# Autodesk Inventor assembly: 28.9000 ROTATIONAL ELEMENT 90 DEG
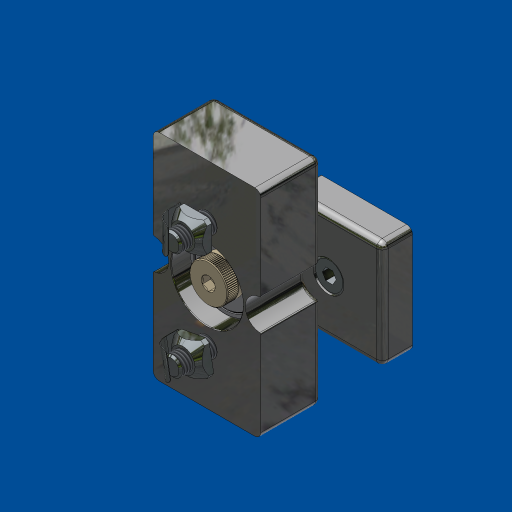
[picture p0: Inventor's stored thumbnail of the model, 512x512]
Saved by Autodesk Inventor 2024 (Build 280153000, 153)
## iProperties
Created: 2022-08
Part Number: 28.9000 ROTATIONAL ELEMENT 90 DEG
Document SubType Name: Assembly
Designer: amoles
Description: ROTATIONAL ELEMENT
Stock Number: ROTATIONAL ELEMENT
Author: amoles
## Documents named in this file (9)
- C:\MY DOCUMENTS\WEBSITE\INVENTOR\PRODUCTS\HINGES LINKS\28.9000 ROTATIONAL ELEMENT\28.9000 ROTATIONAL ELEMENT 90 DEG.iam
- L:\INVENTOR LIBRARIES\PARTS LIBRARY\MACHINE ELEMENTS\BALL BEARINGS\50.9102 5200 2RS DOUBLE ROW ANGULAR CONTACT BEARING 10mm ID - 30MM OD.iam
- L:\INVENTOR LIBRARIES\PARTS LIBRARY\LINKS AND HINGES\SUBCOMPONENTS\28.9000-1 ROTATIONAL ELEMENT BEARING PLATE DOUBLE ROW BEARING.ipt
- L:\INVENTOR LIBRARIES\PARTS LIBRARY\LINKS AND HINGES\SUBCOMPONENTS\28.9000-2 RATATIONAL ELEMENT ROTATING PLATE.ipt
- L:\INVENTOR LIBRARIES\PARTS LIBRARY\FASTENING ELEMENTS\SCREWS CAP\21.1280 M8X22.ipt
- L:\INVENTOR LIBRARIES\PARTS LIBRARY\FASTENING ELEMENTS\NUTS\21.1351_2 M8 SQUARE NUT POS FXG.ipt
- L:\INVENTOR LIBRARIES\PARTS LIBRARY\FASTENING ELEMENTS\SCREWS CAP\21.1208 M8X35.ipt
- L:\INVENTOR LIBRARIES\PARTS LIBRARY\LINKS AND HINGES\SUBCOMPONENTS\28.9000-3 ROTATIONAL ELEMENT WASHER.ipt
- L:\INVENTOR LIBRARIES\PARTS LIBRARY\FASTENING ELEMENTS\SHOULDER SCREWS\21.9608_20 M8 SHOULDER BOLT 20mm.ipt
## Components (13 placed, 8 different names)
1. 50.9102 5200 2RS DOUBLE ROW ANGULAR CONTACT BEARING 10mm ID - 30MM OD:1 [sub-assembly] — Insert:1, Insert:14, Insert:15
2. 28.0090-1 ROTATIONAL ELEMENT BEARING PLATE DOUBLE ROW BEARING:1 — Insert:1, Angle:1, Insert:9, Insert:10, Insert:11, Insert:12, Angle:5
3. 28.9000-2 ROTATIONAL ELEMENT ROTATING PLATE:1 — Mate:2, Insert:5, Insert:6, Insert:7, Insert:8, Angle:3, Angle:4, Mate:4, Mate:5, Angle:5
4. 21.1280 M8X22:1 — Insert:6
5. 21.1280 M8X22:2 — Insert:5
6. 21.1351_2 M8 SQUARE NUT POS FXG:1 — Insert:7, Angle:4
7. 21.1351_2 M8 SQUARE NUT POS FXG:2 — Insert:8, Angle:3
8. 21.1351_2 M8 SQUARE NUT POS FXG:3 — Insert:12
9. 21.1351_2 M8 SQUARE NUT POS FXG:4 — Insert:11
10. 21.1208  M8 x 35:1 — Insert:9
11. 21.1208  M8 x 35:2 — Insert:10
12. 28.9000-3 ROTATIONAL ELEMENT WASHER:2 — Insert:14, Mate:4
13. 21.9608/20 SHOULDER BOLT M8 THRED 10mm SHLDER 20mm LONG:1 — Insert:15, Mate:5, Mate:6
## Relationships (19: Insert 11, Mate 4, Angle 4)
- Insert:1: 50.9102 5200 2RS DOUBLE ROW ANGULAR CONTACT BEARING 10mm ID - 30MM OD:1 ↔ 28.0090-1 ROTATIONAL ELEMENT BEARING PLATE DOUBLE ROW BEARING:1
- Mate:2: 28.9000-2 ROTATIONAL ELEMENT ROTATING PLATE:1
- Angle:1: 28.0090-1 ROTATIONAL ELEMENT BEARING PLATE DOUBLE ROW BEARING:1
- Insert:5: 28.9000-2 ROTATIONAL ELEMENT ROTATING PLATE:1 ↔ 21.1280 M8X22:2
- Insert:6: 28.9000-2 ROTATIONAL ELEMENT ROTATING PLATE:1 ↔ 21.1280 M8X22:1
- Insert:7: 28.9000-2 ROTATIONAL ELEMENT ROTATING PLATE:1 ↔ 21.1351_2 M8 SQUARE NUT POS FXG:1
- Insert:8: 28.9000-2 ROTATIONAL ELEMENT ROTATING PLATE:1 ↔ 21.1351_2 M8 SQUARE NUT POS FXG:2
- Angle:3: 28.9000-2 ROTATIONAL ELEMENT ROTATING PLATE:1 ↔ 21.1351_2 M8 SQUARE NUT POS FXG:2
- Angle:4: 28.9000-2 ROTATIONAL ELEMENT ROTATING PLATE:1 ↔ 21.1351_2 M8 SQUARE NUT POS FXG:1
- Insert:9: 28.0090-1 ROTATIONAL ELEMENT BEARING PLATE DOUBLE ROW BEARING:1 ↔ 21.1208  M8 x 35:1
- Insert:10: 28.0090-1 ROTATIONAL ELEMENT BEARING PLATE DOUBLE ROW BEARING:1 ↔ 21.1208  M8 x 35:2
- Insert:11: 28.0090-1 ROTATIONAL ELEMENT BEARING PLATE DOUBLE ROW BEARING:1 ↔ 21.1351_2 M8 SQUARE NUT POS FXG:4
- Insert:12: 28.0090-1 ROTATIONAL ELEMENT BEARING PLATE DOUBLE ROW BEARING:1 ↔ 21.1351_2 M8 SQUARE NUT POS FXG:3
- Insert:14: 50.9102 5200 2RS DOUBLE ROW ANGULAR CONTACT BEARING 10mm ID - 30MM OD:1 ↔ 28.9000-3 ROTATIONAL ELEMENT WASHER:2
- Mate:4: 28.9000-2 ROTATIONAL ELEMENT ROTATING PLATE:1 ↔ 28.9000-3 ROTATIONAL ELEMENT WASHER:2
- Insert:15: 50.9102 5200 2RS DOUBLE ROW ANGULAR CONTACT BEARING 10mm ID - 30MM OD:1 ↔ 21.9608/20 SHOULDER BOLT M8 THRED 10mm SHLDER 20mm LONG:1
- Mate:5: 28.9000-2 ROTATIONAL ELEMENT ROTATING PLATE:1 ↔ 21.9608/20 SHOULDER BOLT M8 THRED 10mm SHLDER 20mm LONG:1
- Mate:6: 21.9608/20 SHOULDER BOLT M8 THRED 10mm SHLDER 20mm LONG:1
- Angle:5: 28.0090-1 ROTATIONAL ELEMENT BEARING PLATE DOUBLE ROW BEARING:1 ↔ 28.9000-2 ROTATIONAL ELEMENT ROTATING PLATE:1
